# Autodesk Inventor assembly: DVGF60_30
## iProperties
Created: 2010-04
Part Number: DVGF60_30
Document SubType Name: Assembly
Designer: TB
Mass: 1002.9 g
Surface Area: 1678.38 cm^2
Volume: 1002.9 cm^3
Density: 1 g/cm^3
Description: KM DVGF 60/30 - 100 mm
Slaglengde: 100.000 mm
Author: TB
